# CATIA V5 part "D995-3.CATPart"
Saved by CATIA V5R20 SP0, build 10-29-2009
Part number: D995-3
Source: Unknown
Property "ARTICLENO": "D995-3"
Property "BOMINFO": "D995-3"
Property "CODE": "D995-3"
Property "F1": "50.000"
Property "F2": "68.000"
Property "L": "314.000"
Property "L1": "220.000"
Property "L2": "155.000"
Property "L3": "170.000"
Property "LINA": "D995-3"
Property "NB": "D995-3"
Property "NBSYN": "$CODE."
Property "NN": "D995"
Property "NT": "D995"
Property "S": "80.000"
Property "SUPPLIER": "CF"
Bounding box of the stored display mesh (mm): x -22.5 to 22.5, y -331 to 0, z -22.5 to 22.5
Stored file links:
  C:\Users\Utente\Desktop\3D files D995\D995-3.CATPart
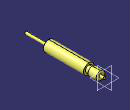
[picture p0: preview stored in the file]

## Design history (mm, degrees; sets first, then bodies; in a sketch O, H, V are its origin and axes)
Body1 "Geometry.1" (main body)
  Solid1 "D995-3.catpart": solid without history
